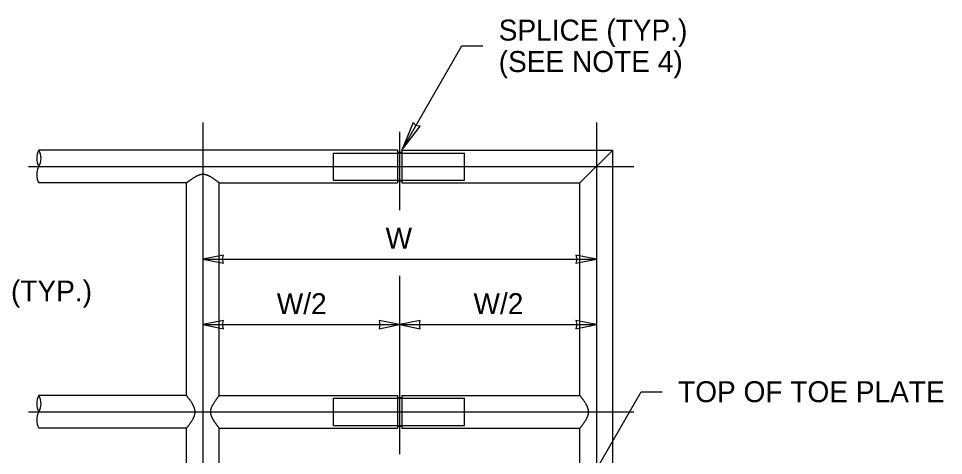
# Model space of a CAD drawing. Extents: x 99862 to 103151, y 100000 to 108076.
# Drawn here: x 101472 to 102177, y 100574 to 100908 of the extents above; entities that cross this region are included whole.
import ezdxf

# ---------------------------------------------------------------- set-up
doc = ezdxf.new("R2010")
doc.units = 0
for name, color, linetype in [('Level 15', 7, 'Continuous'), ('Level 2', 7, 'Continuous'), ('Level 20', 7, 'Continuous'), ('Level 4', 7, 'Continuous')]:
    doc.layers.add(name, color=color, linetype=linetype)

msp = doc.modelspace()

# ---------------------------------------------------------------- linework, layer by layer
at = {"layer": 'Level 15'}
for p, q in [((101764.42, 100807.21), (101810.38, 100886.82)), ((101810.38, 100886.82), (101826.38, 100886.82)), ((101612.87, 100828.46), (101612.87, 100292.12)), ((101912.85, 100828.46), (101912.85, 100292.12)), ((101762.86, 100821.25), (101762.86, 100761.52)), ((101479.85, 100794.71), (101941.35, 100794.71)), ((101612.87, 100724.16), (101912.85, 100724.16)), ((101762.86, 100711.44), (101762.86, 100575.4)), ((101612.87, 100674.16), (101762.87, 100674.16)), ((101762.87, 100674.16), (101912.85, 100674.16)), ((101830.25, 100420.62), (101947.11, 100623.03)), ((101947.11, 100623.03), (101963.11, 100623.03)), ((101479.85, 100607.66), (101941.35, 100607.66))]:
    msp.add_line(p, q, dxfattribs=at)
for points in [[(101764.42, 100807.21), (101778.42, 100825.49), (101775.3, 100826.06), (101773.25, 100828.47)], [(101612.87, 100724.16), (101628.59, 100721.08), (101627.87, 100724.16), (101628.59, 100727.25)], [(101912.85, 100724.16), (101897.12, 100727.25), (101897.85, 100724.16), (101897.12, 100721.08)], [(101612.87, 100674.16), (101628.59, 100671.08), (101627.87, 100674.16), (101628.59, 100677.25)], [(101762.87, 100674.16), (101747.14, 100677.25), (101747.87, 100674.16), (101747.14, 100671.08)], [(101762.87, 100674.16), (101778.59, 100671.08), (101777.87, 100674.16), (101778.59, 100677.25)], [(101912.85, 100674.16), (101897.12, 100677.25), (101897.85, 100674.16), (101897.12, 100671.08)]]:
    msp.add_lwpolyline(points, close=True, dxfattribs=at)
for centre, start, end in [((101498.67, 100800.96), 150, 210), ((101477.02, 100800.96), 330, 30), ((101498.67, 100788.46), 150, 210), ((101498.67, 100613.89), 150, 210), ((101477.02, 100613.89), 330, 30), ((101498.67, 100601.39), 150, 210)]:
    msp.add_arc(centre, 12.5, start, end, dxfattribs=at)
at = {"layer": 'Level 2'}
for p, q in [((101712.3, 100784.35), (101712.3, 100805.06)), ((101712.3, 100805.06), (101812.28, 100805.06)), ((101761.29, 100807.21), (101761.29, 100782.21)), ((101761.29, 100805.65), (101764.42, 100805.65)), ((101764.42, 100807.21), (101764.42, 100782.21)), ((101812.28, 100784.35), (101812.28, 100805.06)), ((101925.35, 100807.21), (101900.35, 100782.21)), ((101712.3, 100784.35), (101812.28, 100784.35)), ((101761.29, 100783.77), (101764.42, 100783.77)), ((101761.29, 100620.14), (101761.29, 100595.14)), ((101764.42, 100620.14), (101764.42, 100595.14)), ((101712.3, 100597.28), (101712.3, 100618)), ((101712.3, 100618), (101812.28, 100618)), ((101761.29, 100618.58), (101764.42, 100618.58)), ((101812.28, 100597.28), (101812.28, 100618)), ((101712.3, 100597.28), (101812.28, 100597.28)), ((101761.29, 100596.7), (101764.42, 100596.7))]:
    msp.add_line(p, q, dxfattribs=at)
for points in [[(101625.37, 100782.21), (101625.37, 100782.21), (101625.37, 100782.21), (101625.37, 100782.21), (101625.37, 100782.22), (101625.29, 100782.27), (101625.17, 100782.37), (101625.01, 100782.5), (101624.91, 100782.56), (101624.89, 100782.58), (101624.84, 100782.63), (101624.68, 100782.75), (101624.33, 100783.01), (101623.95, 100783.3), (101623.64, 100783.53), (101623.54, 100783.6), (101623.34, 100783.76), (101623.01, 100784.01), (101622.4, 100784.46), (101621.74, 100784.93), (101621.3, 100785.22), (101621.02, 100785.41), (101620.87, 100785.51), (101620.41, 100785.8), (101619.8, 100786.21), (101619.17, 100786.6), (101618.48, 100787), (101618.13, 100787.19), (101617.59, 100787.47), (101617.42, 100787.56), (101617.04, 100787.73), (101616.86, 100787.82), (101616.27, 100788.06), (101615.87, 100788.22), (101615.36, 100788.37), (101615.26, 100788.41), (101615.05, 100788.47), (101614.95, 100788.5), (101614.62, 100788.57), (101614.19, 100788.66), (101613.76, 100788.71), (101613.32, 100788.75), (101613.1, 100788.76), (101612.87, 100788.76), (101612.41, 100788.76), (101611.98, 100788.73), (101611.34, 100788.61), (101611.01, 100788.55), (101610.71, 100788.47), (101610.48, 100788.41), (101610.38, 100788.38), (101609.87, 100788.22), (101609.46, 100788.06), (101608.7, 100787.73), (101608.35, 100787.57), (101607.79, 100787.29), (101607.61, 100787.19), (101607.28, 100787), (101606.74, 100786.71), (101605.93, 100786.21), (101605.02, 100785.61), (101604.31, 100785.13), (101603.77, 100784.75), (101603.49, 100784.56), (101603.11, 100784.28), (101602.63, 100783.93), (101602.1, 100783.53), (101601.76, 100783.28), (101601.61, 100783.17), (101601.54, 100783.1), (101601.49, 100783.07), (101601.26, 100782.91), (101600.98, 100782.68), (101600.67, 100782.45), (101600.57, 100782.36), (101600.49, 100782.31), (101600.47, 100782.28), (101600.39, 100782.22), (101600.37, 100782.21), (101600.37, 100782.21), (101600.37, 100782.21)], [(101600.37, 100595.14), (101600.37, 100595.14), (101600.37, 100595.14), (101600.37, 100595.14), (101600.38, 100595.14), (101600.43, 100595.22), (101600.53, 100595.34), (101600.66, 100595.5), (101600.72, 100595.6), (101600.74, 100595.62), (101600.79, 100595.67), (101600.91, 100595.83), (101601.17, 100596.18), (101601.46, 100596.56), (101601.69, 100596.87), (101601.76, 100596.97), (101601.92, 100597.17), (101602.17, 100597.5), (101602.62, 100598.11), (101603.09, 100598.77), (101603.38, 100599.21), (101603.57, 100599.49), (101603.67, 100599.64), (101603.96, 100600.1), (101604.37, 100600.71), (101604.76, 100601.34), (101605.16, 100602.03), (101605.35, 100602.38), (101605.63, 100602.92), (101605.71, 100603.09), (101605.89, 100603.47), (101605.98, 100603.65), (101606.22, 100604.24), (101606.38, 100604.64), (101606.53, 100605.15), (101606.57, 100605.25), (101606.63, 100605.46), (101606.65, 100605.56), (101606.73, 100605.89), (101606.82, 100606.32), (101606.87, 100606.75), (101606.91, 100607.18), (101606.92, 100607.41), (101606.92, 100607.64), (101606.92, 100608.1), (101606.88, 100608.53), (101606.77, 100609.17), (101606.71, 100609.5), (101606.63, 100609.8), (101606.57, 100610.03), (101606.54, 100610.13), (101606.38, 100610.64), (101606.22, 100611.04), (101605.89, 100611.81), (101605.73, 100612.16), (101605.45, 100612.72), (101605.35, 100612.9), (101605.16, 100613.23), (101604.86, 100613.76), (101604.37, 100614.58), (101603.77, 100615.49), (101603.29, 100616.2), (101602.91, 100616.74), (101602.72, 100617.02), (101602.44, 100617.4), (101602.09, 100617.88), (101601.69, 100618.41), (101601.43, 100618.74), (101601.33, 100618.9), (101601.26, 100618.97), (101601.23, 100619.02), (101601.07, 100619.25), (101600.84, 100619.53), (101600.61, 100619.84), (101600.52, 100619.94), (101600.47, 100620.01), (101600.44, 100620.04), (101600.38, 100620.12), (101600.37, 100620.14), (101600.37, 100620.14), (101600.37, 100620.14)], [(101625.37, 100595.14), (101625.37, 100595.14), (101625.37, 100595.14), (101625.37, 100595.14), (101625.36, 100595.14), (101625.31, 100595.22), (101625.2, 100595.34), (101625.08, 100595.5), (101625.01, 100595.6), (101625, 100595.62), (101624.95, 100595.67), (101624.82, 100595.83), (101624.57, 100596.18), (101624.28, 100596.56), (101624.05, 100596.87), (101623.97, 100596.97), (101623.82, 100597.17), (101623.57, 100597.5), (101623.12, 100598.11), (101622.65, 100598.77), (101622.36, 100599.21), (101622.17, 100599.49), (101622.07, 100599.64), (101621.77, 100600.1), (101621.37, 100600.71), (101620.97, 100601.34), (101620.58, 100602.03), (101620.39, 100602.38), (101620.11, 100602.92), (101620.02, 100603.09), (101619.84, 100603.47), (101619.75, 100603.65), (101619.51, 100604.24), (101619.36, 100604.64), (101619.21, 100605.15), (101619.17, 100605.25), (101619.11, 100605.46), (101619.08, 100605.56), (101619.01, 100605.89), (101618.92, 100606.32), (101618.87, 100606.75), (101618.83, 100607.18), (101618.81, 100607.41), (101618.81, 100607.64), (101618.81, 100608.1), (101618.85, 100608.53), (101618.97, 100609.17), (101619.03, 100609.5), (101619.11, 100609.8), (101619.17, 100610.03), (101619.2, 100610.13), (101619.36, 100610.64), (101619.51, 100611.04), (101619.84, 100611.81), (101620.01, 100612.16), (101620.29, 100612.72), (101620.39, 100612.9), (101620.58, 100613.23), (101620.87, 100613.76), (101621.37, 100614.58), (101621.96, 100615.49), (101622.45, 100616.2), (101622.83, 100616.74), (101623.02, 100617.02), (101623.3, 100617.4), (101623.64, 100617.88), (101624.05, 100618.41), (101624.3, 100618.74), (101624.4, 100618.9), (101624.48, 100618.97), (101624.51, 100619.02), (101624.67, 100619.25), (101624.9, 100619.53), (101625.13, 100619.84), (101625.22, 100619.94), (101625.27, 100620.01), (101625.29, 100620.04), (101625.36, 100620.12), (101625.37, 100620.14), (101625.37, 100620.14), (101625.37, 100620.14)], [(101900.35, 100595.14), (101900.35, 100595.14), (101900.35, 100595.14), (101900.35, 100595.14), (101900.36, 100595.14), (101900.41, 100595.22), (101900.51, 100595.34), (101900.64, 100595.5), (101900.7, 100595.6), (101900.72, 100595.62), (101900.77, 100595.67), (101900.89, 100595.83), (101901.15, 100596.18), (101901.44, 100596.56), (101901.67, 100596.87), (101901.74, 100596.97), (101901.9, 100597.17), (101902.15, 100597.5), (101902.6, 100598.11), (101903.07, 100598.77), (101903.36, 100599.21), (101903.55, 100599.49), (101903.65, 100599.64), (101903.94, 100600.1), (101904.35, 100600.71), (101904.74, 100601.34), (101905.14, 100602.03), (101905.33, 100602.38), (101905.61, 100602.92), (101905.7, 100603.09), (101905.87, 100603.47), (101905.96, 100603.65), (101906.2, 100604.24), (101906.36, 100604.64), (101906.51, 100605.15), (101906.55, 100605.25), (101906.61, 100605.46), (101906.64, 100605.56), (101906.71, 100605.89), (101906.8, 100606.32), (101906.85, 100606.75), (101906.89, 100607.18), (101906.9, 100607.41), (101906.9, 100607.64), (101906.9, 100608.1), (101906.86, 100608.53), (101906.75, 100609.17), (101906.69, 100609.5), (101906.61, 100609.8), (101906.55, 100610.03), (101906.52, 100610.13), (101906.36, 100610.64), (101906.2, 100611.04), (101905.87, 100611.81), (101905.71, 100612.16), (101905.43, 100612.72), (101905.33, 100612.9), (101905.14, 100613.23), (101904.84, 100613.76), (101904.35, 100614.58), (101903.75, 100615.49), (101903.27, 100616.2), (101902.89, 100616.74), (101902.7, 100617.02), (101902.42, 100617.4), (101902.07, 100617.88), (101901.67, 100618.41), (101901.41, 100618.74), (101901.31, 100618.9), (101901.24, 100618.97), (101901.21, 100619.02), (101901.05, 100619.25), (101900.82, 100619.53), (101900.59, 100619.84), (101900.5, 100619.94), (101900.45, 100620.01), (101900.42, 100620.04), (101900.36, 100620.12), (101900.35, 100620.14), (101900.35, 100620.14), (101900.35, 100620.14)]]:
    msp.add_open_spline(points, degree=3, dxfattribs=at)
at = {"layer": 'Level 4'}
for p, q in [((101761.29, 100807.21), (101487.85, 100807.21)), ((101764.42, 100807.21), (101925.35, 100807.21)), ((101925.35, 100373.05), (101925.35, 100807.21)), ((101600.37, 100782.21), (101487.85, 100782.21)), ((101600.37, 100620.14), (101600.37, 100782.21)), ((101625.37, 100620.14), (101625.37, 100782.21)), ((101625.37, 100782.21), (101761.29, 100782.21)), ((101764.42, 100782.21), (101900.39, 100782.21)), ((101900.35, 100620.14), (101900.35, 100782.21)), ((101600.37, 100620.14), (101487.85, 100620.14)), ((101625.37, 100620.14), (101761.29, 100620.14)), ((101764.42, 100620.14), (101900.39, 100620.14)), ((101600.37, 100595.14), (101487.85, 100595.14)), ((101600.37, 100373.05), (101600.37, 100595.14)), ((101625.37, 100373.05), (101625.37, 100595.14)), ((101625.37, 100595.14), (101761.29, 100595.14)), ((101764.42, 100595.14), (101900.39, 100595.14)), ((101900.35, 100373.05), (101900.35, 100595.14))]:
    msp.add_line(p, q, dxfattribs=at)

# ---------------------------------------------------------------- texts
at = {"layer": 'Level 20'}
for s, p in [('SPLICE (TYP.)', (101838.38, 100890.82)), ('(SEE NOTE 4)', (101838.38, 100866.82)), ('W', (101752.14, 100732.17)), ('(TYP.)', (101466.54, 100691.84)), ('W/2', (101669.16, 100682.17)), ('W/2', (101819.15, 100682.17)), ('TOP OF TOE PLATE', (101975.11, 100615.03))]:
    msp.add_text(s, height=16, dxfattribs=at).set_placement(p)

doc.saveas('drawing.dxf')
